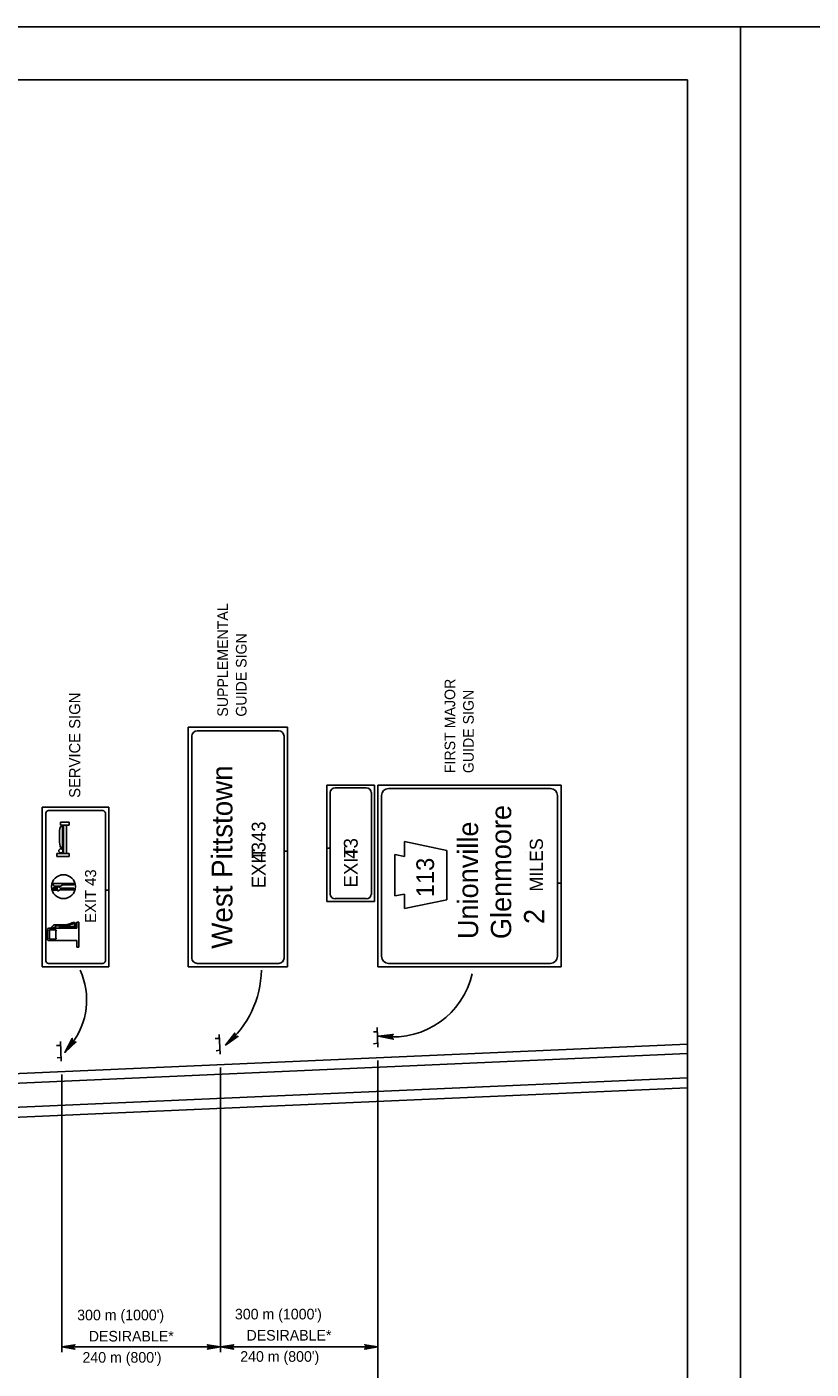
# Model space of a CAD drawing. Extents: x 640994 to 644422, y 298458 to 299646.
# Drawn here: x 642474.1 to 642696.3, y 299265.4 to 299645.6 of the extents above; entities that cross this region are included whole.
import ezdxf

# ---------------------------------------------------------------- set-up
doc = ezdxf.new("R2010")
doc.units = 0
for name, color, linetype in [('1', 7, 'Continuous'), ('2', 7, 'Continuous'), ('XCS-GRID-MIN', 7, 'Continuous')]:
    doc.layers.add(name, color=color, linetype=linetype)

msp = doc.modelspace()

# ---------------------------------------------------------------- linework, layer by layer
at = {"layer": '1'}
for p in [(641875.31, 299630.63), (642661.31, 299066.63)]:
    msp.add_line(p, (642661.31, 299630.63), dxfattribs=at)
at = {"layer": '2'}
for p, q in [((642547.94, 299447.25), (642519.81, 299447.25)), ((642519.81, 299447.25), (642519.81, 299379.38)), ((642522.31, 299446.25), (642522.31, 299446.25)), ((642522.31, 299446.25), (642545.44, 299446.25)), ((642545.44, 299446.25), (642545.44, 299446.25)), ((642547.94, 299412.11), (642547.94, 299447.25)), ((642520.81, 299381.88), (642520.81, 299444.75)), ((642546.94, 299444.75), (642546.94, 299412.11)), ((642559.06, 299413.05), (642559.06, 299430.88)), ((642559.06, 299430.88), (642572.56, 299430.88)), ((642572.56, 299430.88), (642572.56, 299397.88)), ((642625.44, 299430.88), (642573.56, 299430.88)), ((642573.56, 299430.88), (642573.56, 299379.38)), ((642625.44, 299403.13), (642625.44, 299430.88)), ((642560.06, 299428.75), (642560.06, 299413.05)), ((642570.19, 299430.13), (642561.44, 299430.13)), ((642571.69, 299399.88), (642571.69, 299428.75)), ((642574.56, 299382.38), (642574.56, 299427.88)), ((642576.56, 299429.88), (642622.44, 299429.88)), ((642624.44, 299427.88), (642624.44, 299403.13)), ((642478.44, 299379.38), (642478.44, 299424.63)), ((642478.44, 299424.63), (642497.31, 299424.63)), ((642495.56, 299423.63), (642480.19, 299423.63)), ((642497.31, 299424.63), (642497.31, 299401.1)), ((642479.44, 299422.88), (642479.44, 299381.13)), ((642483.56, 299419.5), (642483.56, 299420.38)), ((642483.56, 299420.38), (642486.06, 299420.38)), ((642483.56, 299419.5), (642486.06, 299419.5)), ((642484.44, 299411.5), (642484.44, 299419.5)), ((642485.31, 299411.5), (642485.31, 299419.5)), ((642486.06, 299419.5), (642486.06, 299420.38)), ((642496.31, 299401.1), (642496.31, 299422.88)), ((642484.19, 299413), (642484.19, 299419.25)), ((642484.44, 299415.5), (642484.44, 299415.5)), ((642546.94, 299412.11), (642547.94, 299412.11)), ((642547.94, 299412.11), (642546.94, 299412.11)), ((642546.94, 299412.11), (642546.94, 299381.88)), ((642547.94, 299379.38), (642547.94, 299412.11)), ((642559.06, 299413.05), (642560.06, 299413.05)), ((642560.06, 299413.05), (642559.06, 299413.05)), ((642559.06, 299397.88), (642559.06, 299413.05)), ((642560.06, 299413.05), (642560.06, 299399.88)), ((642565.81, 299414.38), (642565.81, 299414.38)), ((642581.06, 299410.63), (642581.06, 299414.88)), ((642581.06, 299414.88), (642593.06, 299412.38)), ((642593.06, 299412.38), (642593.06, 299405.25)), ((642615.31, 299411.75), (642615.31, 299411.75)), ((642486.06, 299411.5), (642482.56, 299411.5)), ((642482.56, 299410.63), (642482.56, 299411.5)), ((642486.06, 299410.63), (642482.56, 299410.63)), ((642486.06, 299410.63), (642486.06, 299411.5)), ((642578.31, 299405.38), (642578.31, 299411.25)), ((642578.31, 299411.25), (642581.06, 299410.63)), ((642578.31, 299399.5), (642578.31, 299405.38)), ((642583.44, 299404.88), (642583.44, 299404.88)), ((642583.44, 299404.88), (642583.44, 299404.88)), ((642583.44, 299404.88), (642583.44, 299404.88)), ((642583.44, 299404.88), (642583.44, 299404.88)), ((642593.06, 299405.5), (642593.06, 299398.38)), ((642481.44, 299401.75), (642482.56, 299402)), ((642482.81, 299401.63), (642481.44, 299401.75)), ((642482.81, 299401.5), (642481.44, 299401.63)), ((642481.44, 299401.63), (642482.81, 299401.63)), ((642481.44, 299401.38), (642482.44, 299401.5)), ((642482.94, 299401.25), (642481.44, 299401.38)), ((642481.44, 299401.13), (642482.94, 299401.25)), ((642482.81, 299401), (642481.44, 299401.13)), ((642487.31, 299403), (642481.56, 299403)), ((642481.56, 299403), (642481.56, 299402.75)), ((642483.56, 299402.25), (642481.94, 299402.25)), ((642482.44, 299401.5), (642482.81, 299401.5)), ((642487.31, 299401.63), (642483.69, 299401.63)), ((642487.31, 299401.25), (642483.69, 299401.25)), ((642487.31, 299402.63), (642484.19, 299402.63)), ((642496.31, 299401.1), (642497.31, 299401.1)), ((642497.31, 299401.1), (642496.31, 299401.1)), ((642496.31, 299381.13), (642496.31, 299401.1)), ((642497.31, 299401.1), (642497.31, 299379.38)), ((642624.44, 299403.13), (642625.44, 299403.13)), ((642625.44, 299403.13), (642624.44, 299403.13)), ((642624.44, 299403.13), (642624.44, 299382.38)), ((642625.44, 299379.38), (642625.44, 299403.13)), ((642572.56, 299397.88), (642559.06, 299397.88)), ((642561.44, 299398.75), (642570.19, 299398.75)), ((642581.06, 299400), (642578.31, 299399.5)), ((642581.06, 299395.88), (642581.06, 299400)), ((642593.06, 299398.38), (642581.06, 299395.88)), ((642479.94, 299387.25), (642479.94, 299389.88)), ((642488.19, 299390.38), (642480.31, 299390.38)), ((642482.19, 299389.88), (642480.44, 299389.88)), ((642480.44, 299387.5), (642480.44, 299389.75)), ((642480.81, 299390.38), (642481.44, 299391)), ((642481.44, 299390.5), (642481.31, 299390.38)), ((642482.19, 299390.5), (642481.44, 299390.5)), ((642481.94, 299391.25), (642485.19, 299391.25)), ((642482.19, 299391), (642485.19, 299391)), ((642482.19, 299391), (642482.19, 299390.5)), ((642482.31, 299387.5), (642482.31, 299389.63)), ((642483.31, 299390.38), (642483.31, 299390.5)), ((642483.56, 299390.75), (642486.81, 299390.75)), ((642483.56, 299390.38), (642483.56, 299390.38)), ((642483.69, 299390.5), (642487.31, 299390.5)), ((642485.81, 299391.5), (642486.56, 299391.63)), ((642485.94, 299391.13), (642486.69, 299391.38)), ((642488.19, 299390.38), (642488.19, 299392)), ((642488.81, 299392), (642488.19, 299392)), ((642488.81, 299385), (642488.81, 299392)), ((642488.19, 299386.88), (642480.31, 299386.88)), ((642482.19, 299387.25), (642480.44, 299387.25)), ((642488.19, 299385), (642488.19, 299386.88)), ((642488.81, 299385), (642488.19, 299385)), ((642497.31, 299379.38), (642478.44, 299379.38)), ((642480.19, 299380.38), (642495.56, 299380.38)), ((642519.81, 299379.38), (642547.94, 299379.38)), ((642522.31, 299380.38), (642522.31, 299380.38)), ((642545.44, 299380.38), (642522.31, 299380.38)), ((642545.44, 299380.38), (642545.44, 299380.38)), ((642573.56, 299379.38), (642625.44, 299379.38)), ((642622.44, 299380.38), (642576.56, 299380.38)), ((642573.31, 299362.25), (642573.56, 299356.63)), ((642528.56, 299359.13), (642527.44, 299359.13)), ((642528.56, 299360.25), (642528.81, 299354.63)), ((642573.44, 299361), (642572.31, 299361)), ((642170.44, 299333.13), (642661.31, 299354.84)), ((642300.56, 299341.63), (642661.31, 299357.46)), ((642483.56, 299357.13), (642482.44, 299357.13)), ((642483.56, 299358.25), (642483.81, 299352.63)), ((642528.69, 299355.75), (642527.69, 299355.63)), ((642573.56, 299357.75), (642572.31, 299357.63)), ((642483.81, 299353.75), (642482.69, 299353.63)), ((642528.94, 299352.38), (642528.94, 299352.38)), ((642528.94, 299350.88), (642528.94, 299270.25)), ((642573.56, 299354.38), (642573.56, 299354.38)), ((642573.56, 299352.88), (642573.56, 299234.75)), ((642171.94, 299326.5), (642661.31, 299347.96)), ((642483.94, 299348.88), (642483.94, 299270.25)), ((642297.31, 299329.13), (642661.31, 299345.09)), ((642528.94, 299271.75), (642483.94, 299271.75)), ((642573.56, 299271.75), (642528.94, 299271.75))]:
    msp.add_line(p, q, dxfattribs=at)
for points in [[(642487.78, 299358.09), (642487.52, 299358.19), (642484.82, 299355.14), (642487.78, 299358.09), (642488.03, 299358.11), (642484.82, 299355.14), (642487.1, 299358.52), (642486.95, 299358.76), (642484.82, 299355.14), (642486.92, 299359.13), (642486.95, 299358.76)], [(642533.69, 299359.7), (642533.31, 299359.8), (642530.36, 299357.21), (642533.69, 299359.7), (642533.94, 299359.72), (642530.36, 299357.21), (642533.03, 299360.16), (642533.01, 299360.4), (642530.36, 299357.21), (642533, 299360.65), (642533.01, 299360.4)], [(642577.56, 299359.25), (642577.56, 299359.5), (642573.69, 299359.75), (642577.56, 299359.25), (642577.94, 299358.88), (642573.69, 299359.75), (642577.56, 299359.88), (642577.69, 299360.25), (642573.69, 299359.75), (642577.94, 299360.25), (642577.69, 299360.25)], [(642487.44, 299271.25), (642487.31, 299271.5), (642483.94, 299271.75), (642487.44, 299271.25), (642487.69, 299271.13), (642483.94, 299271.75), (642487.31, 299271.88), (642487.44, 299272.13), (642483.94, 299271.75), (642487.69, 299272.38), (642487.44, 299272.13)], [(642525.44, 299272.25), (642525.56, 299272), (642528.94, 299271.75), (642525.44, 299272.25), (642525.19, 299272.38), (642528.94, 299271.75), (642525.56, 299271.63), (642525.44, 299271.38), (642528.94, 299271.75), (642525.19, 299271.13), (642525.44, 299271.38)], [(642532.44, 299271.25), (642532.31, 299271.5), (642528.94, 299271.75), (642532.44, 299271.25), (642532.69, 299271.13), (642528.94, 299271.75), (642532.31, 299271.88), (642532.44, 299272.13), (642528.94, 299271.75), (642532.69, 299272.38), (642532.44, 299272.13)], [(642570.06, 299272.25), (642570.19, 299272), (642573.56, 299271.75), (642570.06, 299272.25), (642569.81, 299272.38), (642573.56, 299271.75), (642570.19, 299271.63), (642570.06, 299271.38), (642573.56, 299271.75), (642569.81, 299271.13), (642570.06, 299271.38)]]:
    msp.add_lwpolyline(points, dxfattribs=at)
for centre, radius in [((642483.71, 299412.25), 0.598), ((642484.44, 299402.1), 3.38)]:
    msp.add_circle(centre, radius, dxfattribs=at)
for centre, radius, start, end in [((642522.31, 299444.75), 1.5, 90, 180), ((642545.44, 299444.75), 1.5, 0, 90), ((642576.56, 299427.88), 2, 90, 180), ((642622.44, 299427.88), 2, 0, 90), ((642480.19, 299422.88), 0.75, 90, 180), ((642495.56, 299422.88), 0.75, 0, 90), ((642484.19, 299418.52), 0.74, 84.1655, 172.9293), ((642498.81, 299416.24), 15.54, 171.2295, 181.1783), ((642502.02, 299416.2), 18.75, 180.8408, 188.1781), ((642484.26, 299413.87), 0.868, 202.8419, 269.9082), ((642481.93, 299402.7), 0.422, 180, 270), ((642482.81, 299401.21), 0.83, 44.7019, 103.537), ((642482.86, 299401.64), 0.724, 261.5401, 313.94), ((642483.74, 299400.8), 0.494, 95.8318, 139.6318), ((642483.69, 299402.09), 0.42, 224.9301, 269.654), ((642483.42, 299402.96), 0.696, 281.1263, 314.137), ((642484.17, 299402.21), 0.369, 83.1408, 137.1102), ((642487.26, 299402.79), 0.218, 261.5053, 98.4947), ((642487.26, 299401.48), 0.195, 258.6255, 101.3745), ((642480.33, 299389.94), 0.405, 97.9024, 178.9277), ((642480.6, 299389.69), 0.228, 107.0861, 183.3769), ((642482.02, 299390.47), 0.826, 95.5404, 137.2088), ((642482.09, 299389.59), 0.327, 355.7148, 73.5391), ((642483.61, 299390.52), 0.265, 89.4256, 167.8581), ((642483.71, 299390.43), 0.0642, 79.1965, 181.8396), ((642484.89, 299393.75), 2.48, 276.6108, 292.2765), ((642484.89, 299393.75), 2.79, 276.6108, 292.2765), ((642487.53, 299389.71), 2.24, 92.3973, 115.3499), ((642487.31, 299390.24), 1.32, 82.2446, 117.6633), ((642486.88, 299392.05), 1.27, 271.1053, 299.4807), ((642487.29, 299391.29), 0.794, 269.2148, 356.6422), ((642487.38, 299391.25), 0.7, 359.2139, 85.3444), ((642487.39, 299391.24), 0.318, 289.9687, 73.0966), ((642480.27, 299387.19), 0.346, 171.6254, 276.5874), ((642480.58, 299387.49), 0.207, 168.286, 258.2569), ((642482.15, 299387.55), 0.262, 276.241, 356.6554), ((642522.31, 299381.88), 1.5, 180, 270), ((642545.44, 299381.88), 1.5, 270, 0), ((642576.56, 299382.38), 2, 180, 270), ((642622.44, 299382.38), 2, 270, 0), ((642480.19, 299381.13), 0.75, 180, 270), ((642470.61, 299370.01), 20.4, 321.9627, 24.5125), ((642495.56, 299381.13), 0.75, 270, 0), ((642512.26, 299378.97), 28.27, 310.2091, 358.9986), ((642577.85, 299382.49), 22.95, 263.5843, 347.307)]:
    msp.add_arc(centre, radius, start, end, dxfattribs=at)
for centre, major_axis, start_param, end_param in [((642561.45, 299428.77), (-1.41, 0), 4.712389, 6.283185), ((642570.24, 299428.77), (-1.41, 0), 3.141593, 4.712389), ((642561.45, 299399.96), (1.41, 0), 3.141593, 4.712389), ((642570.24, 299399.96), (1.41, 0), 4.712389, 6.283185)]:
    msp.add_ellipse(centre, major_axis=major_axis, ratio=0.910229, start_param=start_param, end_param=end_param, dxfattribs=at)
at = {"layer": 'XCS-GRID-MIN'}
for points in [[(641835.31, 299645.63), (642676.31, 299645.63), (642676.31, 299051.63), (641835.31, 299051.63)], [(642676.31, 299645.63), (643517.31, 299645.63), (643517.31, 299051.63), (642676.31, 299051.63)]]:
    msp.add_lwpolyline(points, close=True, dxfattribs=at)

# ---------------------------------------------------------------- texts
at = {"layer": '2'}
for s, height, p in [('SUPPLEMENTAL', 3, (642531.06, 299450.25)), ('GUIDE SIGN', 3, (642536.31, 299450.25)), ('FIRST MAJOR', 3, (642595.44, 299434.25)), ('GUIDE SIGN', 3, (642600.69, 299434.25)), ('SERVICE SIGN', 3.1342, (642489.19, 299427.25)), ('West Pittstown', 5.8747, (642532.31, 299384.5)), ('Glenmoore', 5.743, (642611.31, 299387.25)), ('EXIT 43', 3.918, (642541.69, 299401.63)), ('Unionville', 5.743, (642601.94, 299387.25)), ('     43', 3.918, (642567.81, 299402.75)), ('MILES', 3.75, (642620.31, 299400.75)), ('     43', 3.918, (642541.69, 299401.63)), ('EXIT   ', 3.918, (642567.81, 299401.88)), ('113', 5, (642589.44, 299399.13)), ('EXIT 43', 3.134, (642493.69, 299391.85)), ('  2 ', 5.743, (642620.69, 299387.25))]:
    msp.add_text(s, height=height, rotation=90, dxfattribs=at).set_placement(p)
for s, p in [("300 m (1000')", (642488.33, 299279.28)), ("300 m (1000')", (642533.03, 299279.54)), (' DESIRABLE*', (642490.49, 299273.28)), (' DESIRABLE*', (642535.19, 299273.54)), ("240 m (800')", (642489.83, 299267.28)), ("240 m (800')", (642534.53, 299267.54))]:
    msp.add_text(s, height=3, dxfattribs=at).set_placement(p)

doc.saveas('drawing.dxf')
